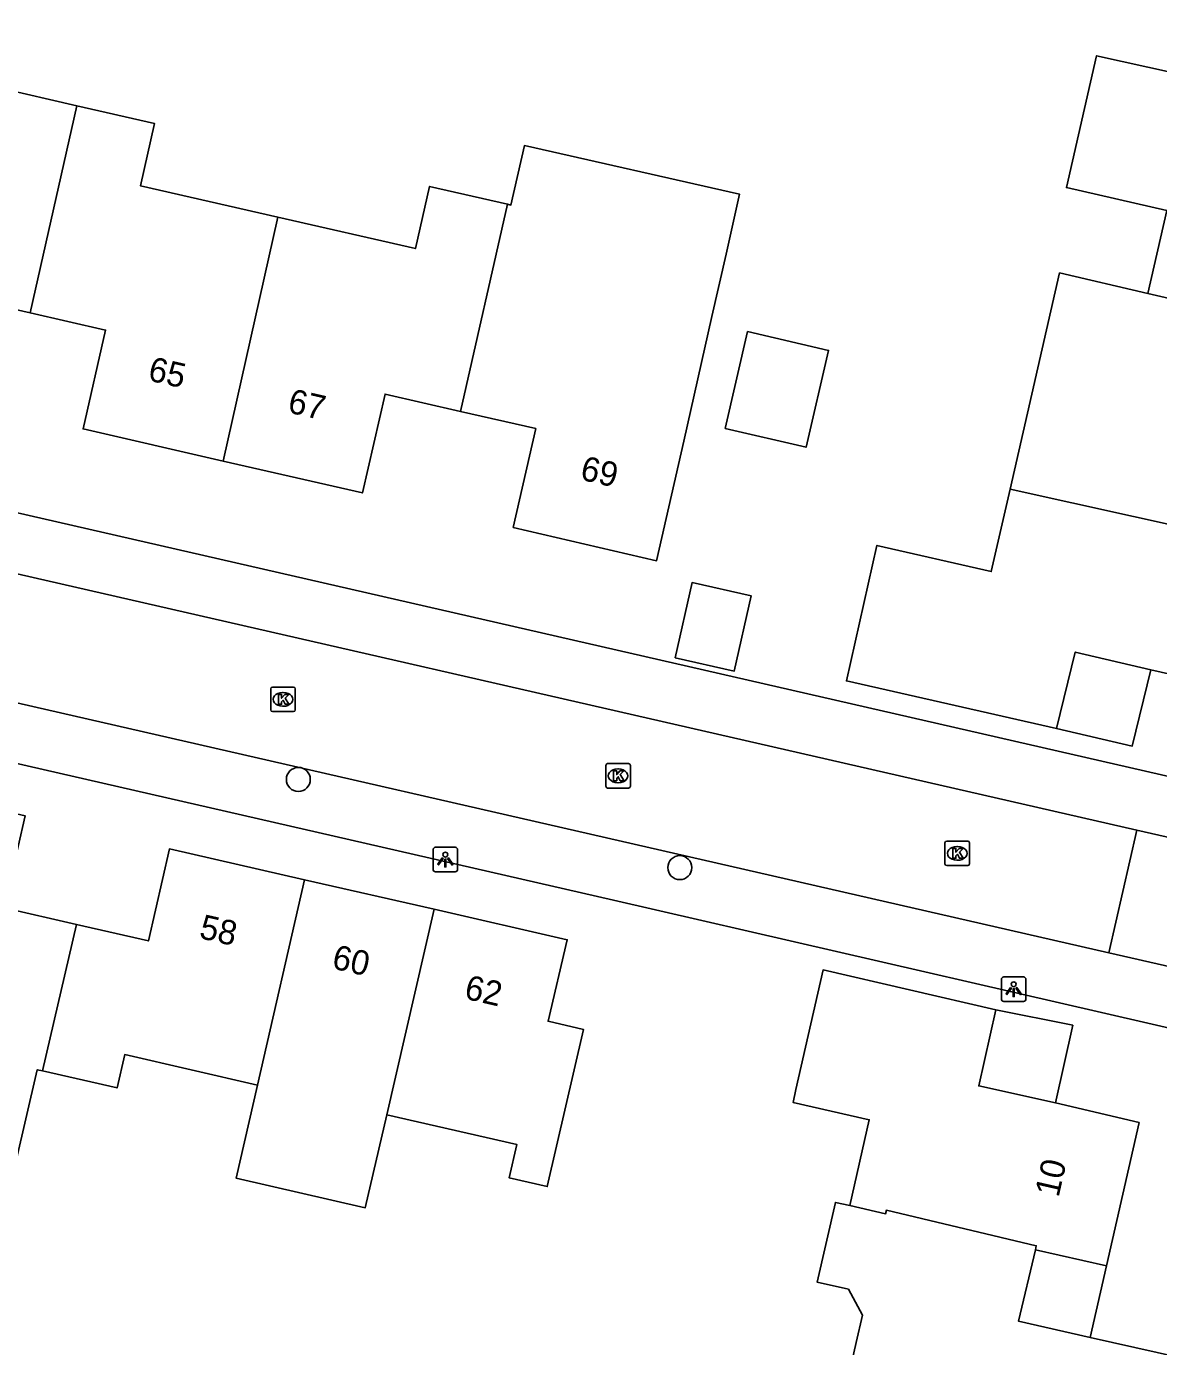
# Model space of a CAD drawing. Extents: x 159628 to 160723, y 388176 to 389416.
# Drawn here: x 160255.4 to 160301.6, y 388620.5 to 388674.3 of the extents above; entities that cross this region are included whole.
import ezdxf

# ---------------------------------------------------------------- set-up
doc = ezdxf.new("R2010")
doc.units = 0
for name, color, linetype in [('IMGEO_Boom', 7, 'Continuous'), ('IMGEO_Kolk', 7, 'Continuous'), ('IMGEO_Lichtpunt', 7, 'Continuous'), ('IMGEO_Pand', 7, 'Continuous'), ('IMGEO_Pand_nummerreeks', 7, 'Continuous'), ('IMGEO_Pand_overbouw', 7, 'Continuous'), ('IMGEO_Rijbaan_lokaal_open', 7, 'Continuous'), ('IMGEO_Voetpad_open', 7, 'Continuous')]:
    doc.layers.add(name, color=color, linetype=linetype)

msp = doc.modelspace()

# ---------------------------------------------------------------- linework, layer by layer
at = {"layer": 'IMGEO_Boom'}
for centre in [(160266.495, 388643.621), (160282.058, 388640.021)]:
    msp.add_circle(centre, 0.489, dxfattribs=at)
at = {"layer": 'IMGEO_Kolk'}
for p, q in [((160265.442, 388647.386), (160266.294, 388647.386)), ((160265.367, 388646.46), (160265.367, 388647.312)), ((160265.855, 388647.166), (160265.88, 388647.166)), ((160266.368, 388647.312), (160266.368, 388646.46)), ((160266.294, 388646.386), (160265.442, 388646.386)), ((160265.878, 388646.606), (160265.853, 388646.606)), ((160279.039, 388643.341), (160279.039, 388644.193)), ((160279.114, 388644.267), (160279.966, 388644.267)), ((160280.04, 388644.193), (160280.04, 388643.341)), ((160279.527, 388644.047), (160279.552, 388644.047)), ((160279.966, 388643.267), (160279.114, 388643.267)), ((160279.55, 388643.487), (160279.525, 388643.487)), ((160292.876, 388640.177), (160292.876, 388641.029)), ((160292.951, 388641.103), (160293.803, 388641.103)), ((160293.877, 388641.029), (160293.877, 388640.177)), ((160293.364, 388640.883), (160293.389, 388640.883)), ((160293.803, 388640.103), (160292.951, 388640.103)), ((160293.387, 388640.323), (160293.362, 388640.323))]:
    msp.add_line(p, q, dxfattribs=at)
for points in [[(160265.442, 388647.386), (160266.294, 388647.386)], [(160265.367, 388646.46), (160265.367, 388647.312)], [(160265.688, 388647.086), (160265.811, 388647.086), (160265.811, 388646.935), (160265.941, 388647.086), (160266.105, 388647.086), (160265.959, 388646.935), (160266.112, 388646.686), (160265.96, 388646.686), (160265.875, 388646.85), (160265.811, 388646.783), (160265.811, 388646.686), (160265.688, 388646.686), (160265.688, 388647.086)], [(160266.368, 388647.312), (160266.368, 388646.46)], [(160266.294, 388646.386), (160265.442, 388646.386)], [(160279.039, 388643.341), (160279.039, 388644.193)], [(160279.114, 388644.267), (160279.966, 388644.267)], [(160280.04, 388644.193), (160280.04, 388643.341)], [(160279.36, 388643.967), (160279.483, 388643.967), (160279.483, 388643.816), (160279.613, 388643.967), (160279.777, 388643.967), (160279.631, 388643.816), (160279.784, 388643.567), (160279.632, 388643.567), (160279.547, 388643.731), (160279.483, 388643.664), (160279.483, 388643.567), (160279.36, 388643.567), (160279.36, 388643.967)], [(160279.966, 388643.267), (160279.114, 388643.267)], [(160292.876, 388640.177), (160292.876, 388641.029)], [(160292.951, 388641.103), (160293.803, 388641.103)], [(160293.877, 388641.029), (160293.877, 388640.177)], [(160293.197, 388640.803), (160293.32, 388640.803), (160293.32, 388640.652), (160293.45, 388640.803), (160293.614, 388640.803), (160293.468, 388640.652), (160293.621, 388640.403), (160293.469, 388640.403), (160293.384, 388640.567), (160293.32, 388640.5), (160293.32, 388640.403), (160293.197, 388640.403), (160293.197, 388640.803)], [(160293.803, 388640.103), (160292.951, 388640.103)]]:
    msp.add_lwpolyline(points, dxfattribs=at)
for centre, start, end in [((160265.444, 388647.31), 91.552, 178.448), ((160265.444, 388647.31), 91.552, 178.448), ((160266.292, 388647.31), 1.552, 88.448), ((160266.292, 388647.31), 1.552, 88.448), ((160265.444, 388646.462), 181.552, 268.448), ((160265.444, 388646.462), 181.552, 268.448), ((160266.292, 388646.462), 271.552, 358.448), ((160266.292, 388646.462), 271.552, 358.448), ((160279.116, 388644.191), 91.552, 178.448), ((160279.116, 388644.191), 91.552, 178.448), ((160279.964, 388644.191), 1.552, 88.448), ((160279.964, 388644.191), 1.552, 88.448), ((160279.116, 388643.343), 181.552, 268.448), ((160279.116, 388643.343), 181.552, 268.448), ((160279.964, 388643.343), 271.552, 358.448), ((160279.964, 388643.343), 271.552, 358.448), ((160292.953, 388641.027), 91.552, 178.448), ((160292.953, 388641.027), 91.552, 178.448), ((160293.801, 388641.027), 1.552, 88.448), ((160293.801, 388641.027), 1.552, 88.448), ((160292.953, 388640.179), 181.552, 268.448), ((160292.953, 388640.179), 181.552, 268.448), ((160293.801, 388640.179), 271.552, 358.448), ((160293.801, 388640.179), 271.552, 358.448)]:
    msp.add_arc(centre, 0.0765, start, end, dxfattribs=at)
for centre, major_axis, ratio, start_param, end_param in [((160265.854, 388646.886), (-0.387, 0.002), 0.722429, 4.712389, 7.853982), ((160265.879, 388646.886), (-0.39, 0.002), 0.717154, 1.570796, 4.712389), ((160279.526, 388643.767), (-0.387, 0.002), 0.722429, 4.712389, 7.853982), ((160279.551, 388643.767), (-0.39, 0.002), 0.717154, 1.570796, 4.712389), ((160293.363, 388640.603), (-0.387, 0.002), 0.722429, 4.712389, 7.853982), ((160293.388, 388640.603), (-0.39, 0.002), 0.717154, 1.570796, 4.712389)]:
    msp.add_ellipse(centre, major_axis=major_axis, ratio=ratio, start_param=start_param, end_param=end_param, dxfattribs=at)
at = {"layer": 'IMGEO_Lichtpunt'}
for p, q in [((160271.994, 388640.755), (160271.994, 388639.948)), ((160271.994, 388640.755), (160271.994, 388639.948)), ((160272.896, 388640.85), (160272.088, 388640.85)), ((160272.896, 388640.85), (160272.088, 388640.85)), ((160272.99, 388639.948), (160272.99, 388640.755)), ((160272.99, 388639.948), (160272.99, 388640.755)), ((160272.088, 388639.854), (160272.896, 388639.854)), ((160272.088, 388639.854), (160272.896, 388639.854)), ((160296.083, 388635.56), (160295.275, 388635.56)), ((160296.083, 388635.56), (160295.275, 388635.56)), ((160295.181, 388635.465), (160295.181, 388634.658)), ((160295.181, 388635.465), (160295.181, 388634.658)), ((160296.177, 388634.658), (160296.177, 388635.465)), ((160296.177, 388634.658), (160296.177, 388635.465)), ((160295.275, 388634.564), (160296.083, 388634.564)), ((160295.275, 388634.564), (160296.083, 388634.564))]:
    msp.add_line(p, q, dxfattribs=at)
for points in [[(160272.368, 388640.419), (160272.407, 388640.391), (160272.219, 388640.129), (160272.181, 388640.156), (160272.368, 388640.419)], [(160272.47, 388640.371), (160272.517, 388640.371), (160272.517, 388640.049), (160272.47, 388640.049), (160272.47, 388640.371)], [(160272.58, 388640.391), (160272.618, 388640.418), (160272.805, 388640.156), (160272.766, 388640.128), (160272.58, 388640.391)], [(160295.555, 388635.129), (160295.594, 388635.101), (160295.406, 388634.839), (160295.368, 388634.866), (160295.555, 388635.129)], [(160295.657, 388635.081), (160295.704, 388635.081), (160295.704, 388634.759), (160295.657, 388634.759), (160295.657, 388635.081)], [(160295.767, 388635.101), (160295.805, 388635.128), (160295.992, 388634.866), (160295.953, 388634.838), (160295.767, 388635.101)]]:
    msp.add_lwpolyline(points, dxfattribs=at)
for centre in [(160272.493, 388640.553), (160295.68, 388635.263)]:
    msp.add_circle(centre, 0.0994, dxfattribs=at)
for centre, start, end in [((160272.088, 388640.755), 90, 180), ((160272.088, 388640.755), 90, 180), ((160272.896, 388640.755), 0, 90), ((160272.896, 388640.755), 0, 90), ((160272.088, 388639.948), 180, 270), ((160272.088, 388639.948), 180, 270), ((160272.896, 388639.948), 270, 0), ((160272.896, 388639.948), 270, 360), ((160295.275, 388635.465), 90, 180), ((160295.275, 388635.465), 90, 180), ((160296.083, 388635.465), 0, 90), ((160296.083, 388635.465), 0, 90), ((160295.275, 388634.658), 180, 270), ((160295.275, 388634.658), 180, 270), ((160296.083, 388634.658), 270, 0), ((160296.083, 388634.658), 270, 360)]:
    msp.add_arc(centre, 0.0946, start, end, dxfattribs=at)
at = {"layer": 'IMGEO_Pand'}
for points in [[(160248.089, 388670.577), (160248.919, 388674.342), (160254.559, 388673.053), (160254.28, 388671.831), (160257.458, 388671.104)], [(160301.158, 388663.45), (160301.93, 388666.828), (160297.833, 388667.765), (160299.063, 388673.147), (160306.51, 388671.5)], [(160257.458, 388671.104), (160255.552, 388662.652)], [(160257.458, 388671.104), (160260.631, 388670.378), (160260.051, 388667.842), (160265.661, 388666.559)], [(160275.024, 388667.088), (160275.167, 388667.055), (160275.722, 388669.483), (160284.5, 388667.494), (160283.945, 388665.048), (160283.37, 388662.51), (160282.216, 388657.417), (160281.11, 388652.54), (160275.26, 388653.9), (160276.184, 388657.932), (160273.108, 388658.637)], [(160265.661, 388666.559), (160271.272, 388665.276), (160271.852, 388667.813), (160275.024, 388667.088)], [(160275.024, 388667.088), (160273.108, 388658.637)], [(160263.431, 388656.61), (160265.661, 388666.559)], [(160295.534, 388655.466), (160297.551, 388664.288), (160301.158, 388663.45)], [(160255.552, 388662.652), (160252.478, 388663.352), (160251.56, 388659.32), (160245.863, 388660.627)], [(160311.621, 388661.018), (160301.158, 388663.45)], [(160263.431, 388656.61), (160257.71, 388657.92), (160258.628, 388661.952), (160255.552, 388662.652)], [(160283.907, 388657.94), (160287.213, 388657.174), (160288.128, 388661.126), (160284.822, 388661.892), (160283.907, 388657.94)], [(160273.108, 388658.637), (160270.034, 388659.342), (160269.11, 388655.31), (160263.431, 388656.61)], [(160304.942, 388653.365), (160306.021, 388653.118), (160304.705, 388647.322), (160301.277, 388648.089), (160298.191, 388648.813), (160297.431, 388645.704), (160288.856, 388647.636), (160290.102, 388653.168), (160294.765, 388652.103), (160295.534, 388655.466)], [(160295.534, 388655.466), (160303.09, 388653.789), (160304.942, 388653.365)], [(160281.869, 388648.581), (160282.559, 388651.648), (160284.973, 388651.104), (160284.282, 388648.037), (160281.869, 388648.581)], [(160249.823, 388643.4), (160255.355, 388642.133), (160254.497, 388638.382), (160257.439, 388637.708)], [(160257.439, 388637.708), (160260.38, 388637.034), (160261.238, 388640.785), (160266.747, 388639.527)], [(160266.747, 388639.527), (160264.825, 388631.151)], [(160266.747, 388639.527), (160272.032, 388638.321)], [(160272.032, 388638.321), (160277.468, 388637.08), (160276.682, 388633.756), (160278.133, 388633.412), (160276.647, 388627.008), (160275.1, 388627.362), (160275.412, 388628.723), (160270.1, 388629.941)], [(160270.1, 388629.941), (160272.032, 388638.321)], [(160256.061, 388631.727), (160257.439, 388637.708)], [(160288.992, 388626.231), (160289.79, 388629.733), (160286.677, 388630.442), (160286.797, 388630.97), (160287.907, 388635.845), (160294.955, 388634.218), (160294.256, 388631.114), (160297.384, 388630.425), (160300.795, 388629.62), (160299.463, 388623.77), (160296.564, 388624.425)], [(160264.825, 388631.151), (160259.412, 388632.392), (160259.1, 388631.031), (160256.061, 388631.727)], [(160256.061, 388631.727), (160255.84, 388631.778), (160254.962, 388627.948), (160251.672, 388628.702), (160252.087, 388630.514), (160247.166, 388631.642)], [(160270.1, 388629.941), (160269.225, 388626.147), (160263.954, 388627.357), (160264.825, 388631.151)], [(160288.515, 388617.399), (160289.255, 388620.645), (160289.51, 388621.764), (160288.938, 388622.817), (160287.663, 388623.107), (160288.405, 388626.365), (160288.992, 388626.231)], [(160288.992, 388626.231), (160290.452, 388625.898), (160290.487, 388626.044), (160296.604, 388624.594), (160296.564, 388624.425)], [(160296.564, 388624.425), (160295.881, 388621.516), (160298.806, 388620.857), (160302.444, 388620.037), (160301.127, 388614.338)]]:
    msp.add_lwpolyline(points, dxfattribs=at)
at = {"layer": 'IMGEO_Pand_overbouw'}
for points in [[(160301.277, 388648.089), (160298.191, 388648.813), (160297.431, 388645.704), (160300.517, 388644.979)], [(160297.384, 388630.425), (160298.093, 388633.594), (160294.955, 388634.218), (160294.256, 388631.114)], [(160298.806, 388620.857), (160299.463, 388623.77), (160296.564, 388624.425), (160295.881, 388621.516)]]:
    msp.add_lwpolyline(points, close=True, dxfattribs=at)
at = {"layer": 'IMGEO_Rijbaan_lokaal_open'}
for points in [[(160243.072, 388654.745), (160300.711, 388641.549)], [(160299.566, 388636.545), (160241.925, 388649.731)], [(160299.566, 388636.545), (160300.711, 388641.549)], [(160300.711, 388641.549), (160303.271, 388640.963)], [(160302.126, 388635.959), (160299.566, 388636.545)]]:
    msp.add_lwpolyline(points, dxfattribs=at)
at = {"layer": 'IMGEO_Voetpad_open'}
for points in [[(160217.738, 388663.033), (160308.833, 388642.18)], [(160306.653, 388632.407), (160279.35, 388638.697), (160215.058, 388653.423)]]:
    msp.add_lwpolyline(points, dxfattribs=at)

# ---------------------------------------------------------------- texts
at = {"layer": 'IMGEO_Pand_nummerreeks'}
for s, rotation, p in [('65', 347.1045, (160260.317, 388659.908)), ('67', 347.1045, (160266.017, 388658.603)), ('69', 346.9124, (160277.951, 388655.862)), ('58', 347.1408, (160262.411, 388637.153)), ('60', 347.1428, (160267.821, 388635.918)), ('62', 347.1408, (160273.225, 388634.684)), ('10', 77.1729, (160297.509, 388626.541))]:
    msp.add_text(s, height=1, rotation=rotation, dxfattribs=at).set_placement(p)

doc.saveas('drawing.dxf')
